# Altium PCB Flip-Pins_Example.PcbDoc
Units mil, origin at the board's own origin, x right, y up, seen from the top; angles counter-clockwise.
Board outline 3000 x 3000 mil, 2 copper layers (Top Layer, Bottom Layer), stack 62 mil thick; 12 components, 0 nets, 168 pads, 0 vias.
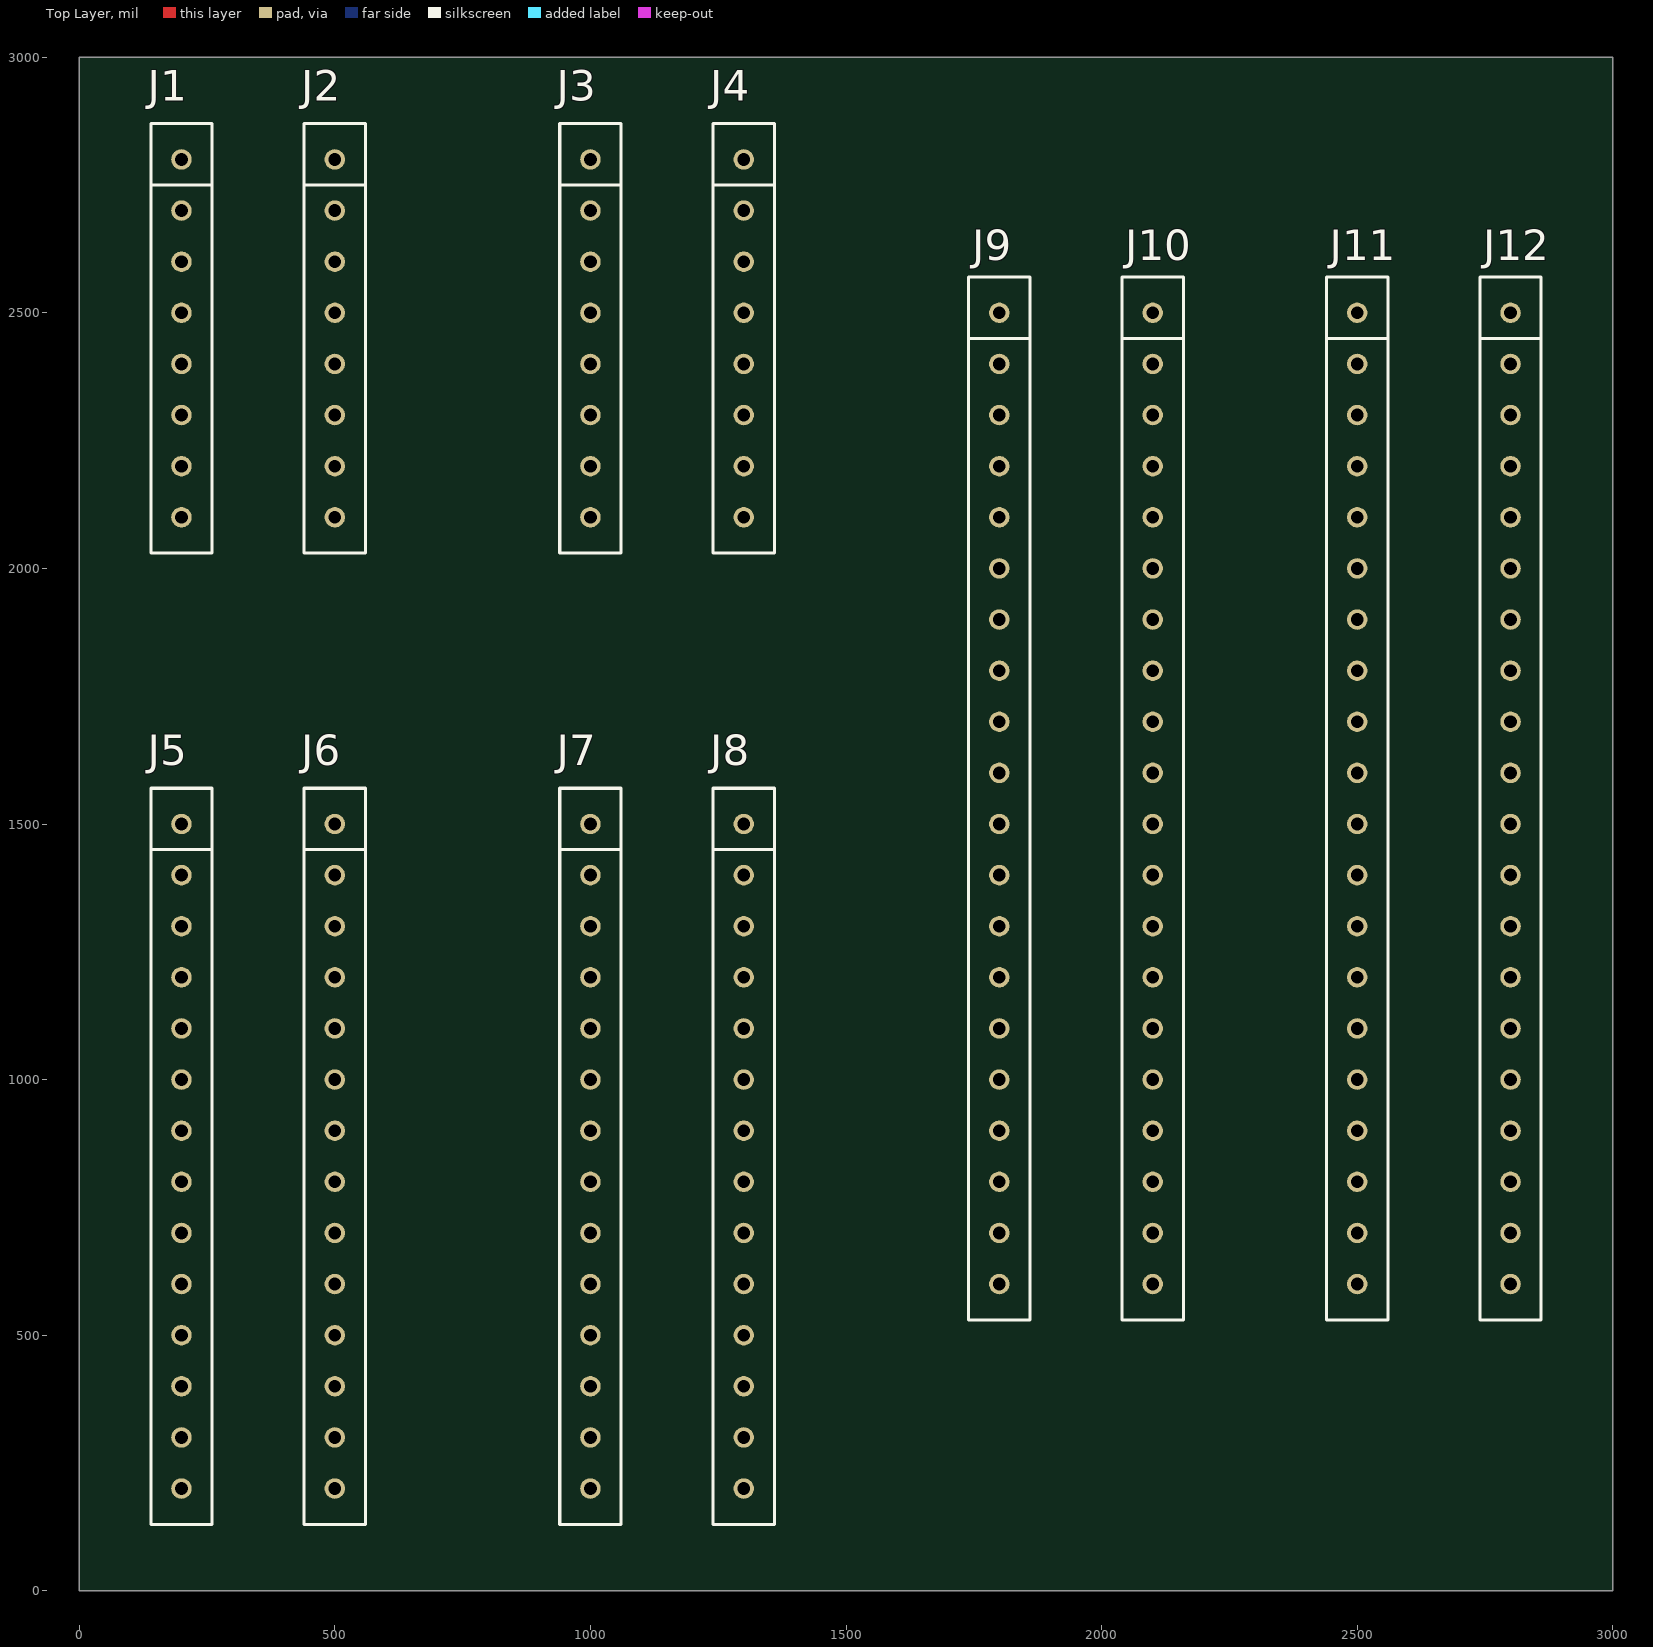
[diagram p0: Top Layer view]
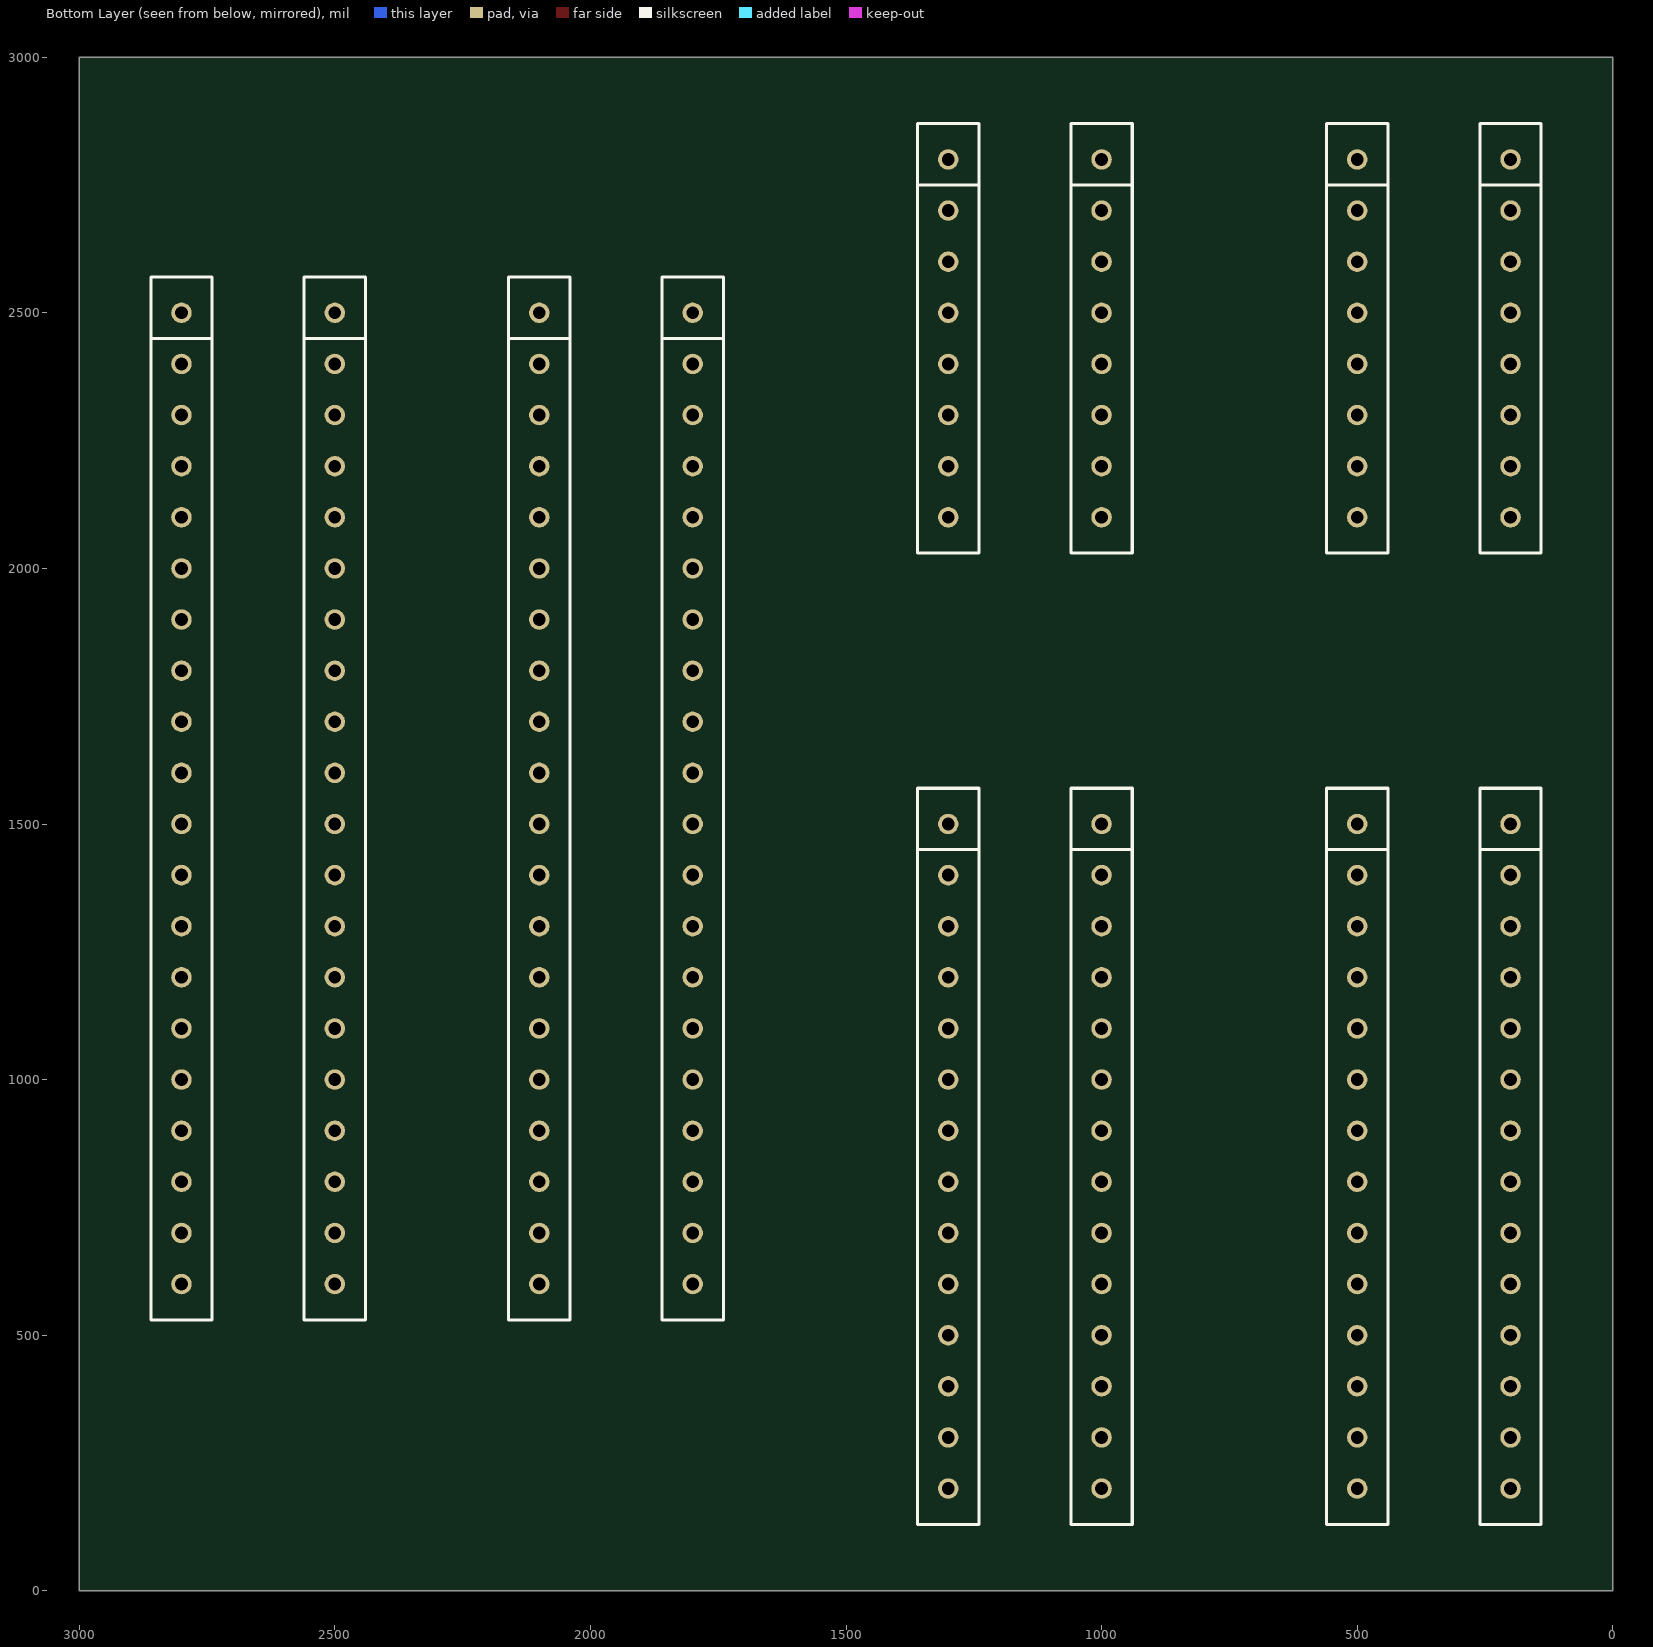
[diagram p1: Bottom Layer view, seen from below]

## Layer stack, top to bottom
Top Layer: signal copper 1.4
Dielectric: core 59.2, FR-4, Dk 4.8
Bottom Layer: signal copper 1.4

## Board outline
0,0 0,3000 3000,3000 3000,0 0,0

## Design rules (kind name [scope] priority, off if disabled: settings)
Clearance [All] p1: gap=10
PolygonConnect [All] p1: connectstyle=Relief reliefconductorwidth=10 reliefentries=4 polygonreliefangle="90 Angle"
RoutingVias [All] p1: holewidth=28 width=50 viastyle="Through Hole" minholewidth=28 minwidth=50 maxholewidth=28 maxwidth=50
SilkscreenOverComponentPads [All] p1: minsilkscreentomaskgap=10
SolderMaskExpansion [All] p1: expansion=4
Width [All] p1: maxlimit=10 minlimit=10 preferedwidth=10
27 further rules are at their usual default settings.

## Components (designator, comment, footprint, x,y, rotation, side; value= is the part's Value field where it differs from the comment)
J1 "Flip-Pins 8" FLIP-PINS-08 200,2800 r0 top
J2 "Flip-Pins 8" FLIP-PINS-08 500,2800 r0 top
J3 "Flip-Pins 8" FLIP-PINS-08_ALIGNER 1000,2800 r0 top
J4 "Flip-Pins 8" FLIP-PINS-08_ALIGNER 1300,2800 r0 top
J5 "Flip-Pins 14" FLIP-PINS-14 200,1500 r0 top
J6 "Flip-Pins 14" FLIP-PINS-14 500,1500 r0 top
J7 "Flip-Pins 14" FLIP-PINS-14_ALIGNER 1000,1500 r0 top
J8 "Flip-Pins 14" FLIP-PINS-14_ALIGNER 1300,1500 r0 top
J9 "Flip-Pins 20" FLIP-PINS-20 1800,2500 r0 top
J10 "Flip-Pins 20" FLIP-PINS-20 2100,2500 r0 top
J11 "Flip-Pins 20" FLIP-PINS-20_ALIGNER 2500,2500 r0 top
J12 "Flip-Pins 20" FLIP-PINS-20_ALIGNER 2800,2500 r0 top

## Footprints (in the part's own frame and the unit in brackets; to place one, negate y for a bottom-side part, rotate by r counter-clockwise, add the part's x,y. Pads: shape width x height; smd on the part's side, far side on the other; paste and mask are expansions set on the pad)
FLIP-PINS-08 [mil] "Flip-Pins 8 pins"
  round 40 hole 25: 1(0,0) 2(0,-100) 3(0,-200) 4(0,-300) 5(0,-400) 6(0,-500) 7(0,-600) 8(0,-700)
  silkscreen extent -60,-770 60,70, body extent -8,-740 8,40, height 240
FLIP-PINS-08_ALIGNER [mil] "Flip-Pins 8 pins with Aligner"
  round 40 hole 25: 1(0,0) 2(0,-100) 3(0,-200) 4(0,-300) 5(0,-400) 6(0,-500) 7(0,-600) 8(0,-700)
  silkscreen extent -60,-770 60,70, body extent -47,-760 47,60, height 240
FLIP-PINS-14 [mil] "Flip-Pins 14 pins"
  round 40 hole 25: 1(0,0) 2(0,-100) 3(0,-200) 4(0,-300) 5(0,-400) 6(0,-500) 7(0,-600) 8(0,-700) 9(0,-800) 10(0,-900) 11(0,-1000) 12(0,-1100) 13(0,-1200) 14(0,-1300)
  silkscreen extent -60,-1370 60,70, body extent -8,-1340 8,40, height 240
FLIP-PINS-14_ALIGNER [mil] "Flip-Pins 14 pins with Aligner"
  round 40 hole 25: 1(0,0) 2(0,-100) 3(0,-200) 4(0,-300) 5(0,-400) 6(0,-500) 7(0,-600) 8(0,-700) 9(0,-800) 10(0,-900) 11(0,-1000) 12(0,-1100) 13(0,-1200) 14(0,-1300)
  silkscreen extent -60,-1370 60,70, body extent -47,-1360 47,60, height 240
FLIP-PINS-20 [mil] "Flip-Pins 20 pins"
  round 40 hole 25: 1(0,0) 2(0,-100) 3(0,-200) 4(0,-300) 5(0,-400) 6(0,-500) 7(0,-600) 8(0,-700) 9(0,-800) 10(0,-900) 11(0,-1000) 12(0,-1100) 13(0,-1200) 14(0,-1300) 15(0,-1400) 16(0,-1500) 17(0,-1600) 18(0,-1700) 19(0,-1800) 20(0,-1900)
  silkscreen extent -60,-1970 60,70, body extent -8,-1940 8,40, height 240
FLIP-PINS-20_ALIGNER [mil] "Flip-Pins 20 pins with Aligner"
  round 40 hole 25: 1(0,0) 2(0,-100) 3(0,-200) 4(0,-300) 5(0,-400) 6(0,-500) 7(0,-600) 8(0,-700) 9(0,-800) 10(0,-900) 11(0,-1000) 12(0,-1100) 13(0,-1200) 14(0,-1300) 15(0,-1400) 16(0,-1500) 17(0,-1600) 18(0,-1700) 19(0,-1800) 20(0,-1900)
  silkscreen extent -60,-1970 60,70, body extent -47,-1960 47,60, height 240

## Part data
J1 J2 J3 J4: library part "J Flip-Pins-08"
J5 J6 J7 J8: library part "J Flip-Pins-14"
J9 J10 J11 J12: library part "J Flip-Pins-20"

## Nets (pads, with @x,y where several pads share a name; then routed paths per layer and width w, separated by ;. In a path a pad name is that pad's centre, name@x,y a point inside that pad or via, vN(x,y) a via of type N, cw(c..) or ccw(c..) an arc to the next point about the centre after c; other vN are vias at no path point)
pads on no net: J1.1 J1.2 J1.3 J1.4 J1.5 J1.6 J1.7 J1.8 J2.1 J2.2 J2.3 J2.4 J2.5 J2.6 J2.7 J2.8 J3.1 J3.2 J3.3 J3.4 J3.5 J3.6 J3.7 J3.8 J4.1 J4.2 J4.3 J4.4 J4.5 J4.6 J4.7 J4.8 J5.1 J5.2 J5.3 J5.4 J5.5 J5.6 J5.7 J5.8 J5.9 J5.10 J5.11 J5.12 J5.13 J5.14 J6.1 J6.2 J6.3 J6.4 J6.5 J6.6 J6.7 J6.8 J6.9 J6.10 J6.11 J6.12 J6.13 J6.14 J7.1 J7.2 J7.3 J7.4 J7.5 J7.6 J7.7 J7.8 J7.9 J7.10 J7.11 J7.12 J7.13 J7.14 J8.1 J8.2 J8.3 J8.4 J8.5 J8.6 J8.7 J8.8 J8.9 J8.10 J8.11 J8.12 J8.13 J8.14 J9.1 J9.2 J9.3 J9.4 J9.5 J9.6 J9.7 J9.8 J9.9 J9.10 J9.11 J9.12 J9.13 J9.14 J9.15 J9.16 J9.17 J9.18 J9.19 J9.20 J10.1 J10.2 J10.3 J10.4 J10.5 J10.6 J10.7 J10.8 J10.9 J10.10 J10.11 J10.12 J10.13 J10.14 J10.15 J10.16 J10.17 J10.18 J10.19 J10.20 J11.1 J11.2 J11.3 J11.4 J11.5 J11.6 J11.7 J11.8 J11.9 J11.10 J11.11 J11.12 J11.13 J11.14 J11.15 J11.16 J11.17 J11.18 J11.19 J11.20 J12.1 J12.2 J12.3 J12.4 J12.5 J12.6 J12.7 J12.8 J12.9 J12.10 J12.11 J12.12 J12.13 J12.14 J12.15 J12.16 J12.17 J12.18 J12.19 J12.20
